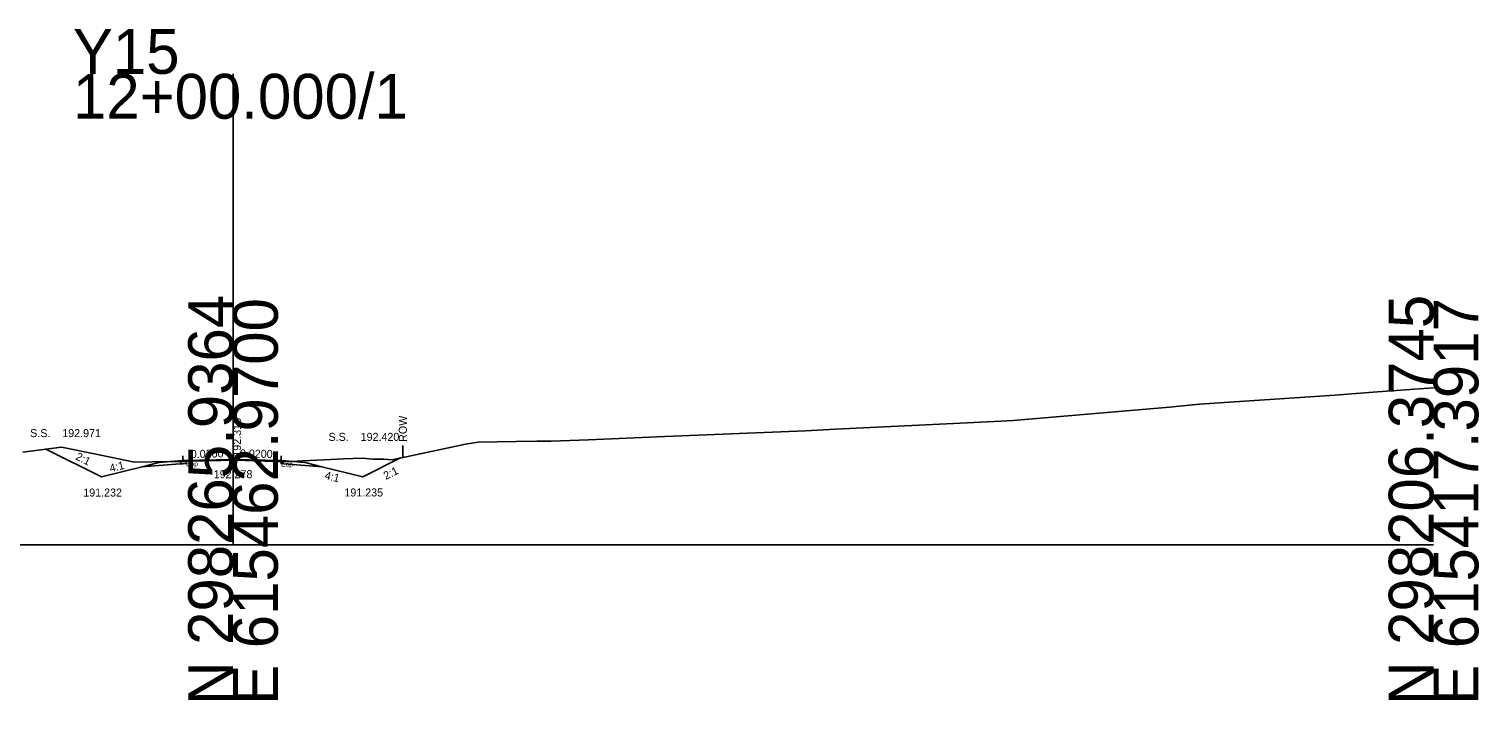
# Model space of a CAD drawing. Extents: x 517327 to 517505, y 114839 to 116885.
# Drawn here: x 517414.6 to 517505.2, y 116338.7 to 116380.6 of the extents above; entities that cross this region are included whole.
import ezdxf

# ---------------------------------------------------------------- set-up
doc = ezdxf.new("R2010")
doc.units = 0
for name, color, linetype in [('Exist XS Ground Line', 7, 'Continuous'), ('Old_Level_60', 7, 'Continuous'), ('Old_Level_63', 7, 'Continuous'), ('Prop XS Dump Level', 7, 'Continuous'), ('Prop XS Earthwork Shape', 7, 'Continuous'), ('Prop XS Elevation Labels', 7, 'Continuous'), ('Prop XS EOT Tick Mark', 7, 'Continuous'), ('Prop XS Exc Vertical Line 2', 7, 'Continuous'), ('Prop XS Finish Grade', 7, 'Continuous'), ('Prop XS Finish Grade Earthwork', 7, 'Continuous'), ('Prop XS Finish Grade Pavement', 7, 'Continuous'), ('Prop XS Hydro Elevations', 7, 'Continuous'), ('Prop XS Label Text', 7, 'Continuous'), ('Prop XS Pvmt Edge Slope', 7, 'Continuous'), ('Prop XS SE Text', 7, 'Continuous'), ('Prop XS Side Slope Text', 7, 'Continuous'), ('Prop XS Subgrade Earthwork', 7, 'Continuous'), ('Prop XS Suitable Common Exc Shape', 7, 'Continuous')]:
    doc.layers.add(name, color=color, linetype=linetype)

msp = doc.modelspace()

# ---------------------------------------------------------------- linework, layer by layer
at = {"layer": 'Exist XS Ground Line'}
for p, q in [((517496.208, 116357.708), (517498.866, 116357.912)), ((517498.866, 116357.912), (517502.365, 116358.167)), ((517476.097, 116356.129), (517485.868, 116356.954)), ((517485.868, 116356.954), (517487.752, 116357.134)), ((517487.752, 116357.134), (517496.208, 116357.708)), ((517465.004, 116355.581), (517472.38, 116355.938)), ((517472.38, 116355.938), (517475.332, 116356.09)), ((517475.332, 116356.09), (517476.097, 116356.129)), ((517449.569, 116354.918), (517454.336, 116355.115)), ((517454.336, 116355.115), (517463.12, 116355.475)), ((517463.12, 116355.475), (517465.004, 116355.581)), ((517414.235, 116354.149), (517416.658, 116354.466)), ((517416.658, 116354.466), (517418.601, 116354.054)), ((517437.316, 116353.676), (517441.897, 116354.636)), ((517441.897, 116354.636), (517442.676, 116354.764)), ((517442.676, 116354.764), (517445.036, 116354.813)), ((517445.036, 116354.813), (517446.339, 116354.823)), ((517446.339, 116354.823), (517447.246, 116354.824)), ((517447.246, 116354.824), (517449.569, 116354.918)), ((517418.601, 116354.054), (517421.204, 116353.527)), ((517421.204, 116353.527), (517423.427, 116353.56)), ((517423.427, 116353.56), (517424.439, 116353.566)), ((517424.439, 116353.566), (517424.822, 116353.576)), ((517424.822, 116353.576), (517427.494, 116353.646)), ((517427.494, 116353.646), (517429.958, 116353.557)), ((517429.958, 116353.557), (517430.376, 116353.545)), ((517430.376, 116353.545), (517431.07, 116353.572)), ((517431.07, 116353.572), (517431.699, 116353.599)), ((517431.699, 116353.599), (517433.06, 116353.671)), ((517433.06, 116353.671), (517434.29, 116353.722)), ((517434.29, 116353.722), (517435.426, 116353.775)), ((517435.426, 116353.775), (517436.094, 116353.704)), ((517436.094, 116353.704), (517436.795, 116353.701)), ((517436.795, 116353.701), (517437.316, 116353.676))]:
    msp.add_line(p, q, dxfattribs=at)
at = {"layer": 'Old_Level_63'}
for p, q in [((517427.365, 116348.365), (517427.365, 116377.77)), ((517352.365, 116348.365), (517427.365, 116348.365)), ((517427.365, 116348.365), (517502.365, 116348.365))]:
    msp.add_line(p, q, dxfattribs=at)
at = {"layer": 'Prop XS Dump Level'}
for p, q in [((517424.239, 116353.617), (517427.365, 116353.68)), ((517427.365, 116353.68), (517430.365, 116353.62))]:
    msp.add_line(p, q, dxfattribs=at)
at = {"layer": 'Prop XS Earthwork Shape'}
for points in [[(517415.661, 116354.336), (517416.658, 116354.466), (517418.601, 116354.054), (517421.204, 116353.527), (517423.427, 116353.56), (517424.44, 116353.567), (517424.438, 116353.431), (517424.239, 116353.427), (517424.045, 116353.423), (517422.739, 116353.319), (517421.69, 116353.235), (517419.139, 116352.597)], [(517435.426, 116353.775), (517436.094, 116353.704), (517436.795, 116353.701), (517437.316, 116353.676), (517437.836, 116353.785), (517435.465, 116352.6), (517432.914, 116353.237), (517431.865, 116353.321), (517430.559, 116353.426), (517430.365, 116353.43), (517430.363, 116353.546), (517431.07, 116353.572), (517431.699, 116353.599), (517433.06, 116353.671), (517434.29, 116353.722)]]:
    msp.add_lwpolyline(points, close=True, dxfattribs=at)
at = {"layer": 'Prop XS EOT Tick Mark'}
for p, q in [((517424.239, 116353.922), (517424.239, 116353.617)), ((517430.365, 116353.62), (517430.365, 116353.924))]:
    msp.add_line(p, q, dxfattribs=at)
at = {"layer": 'Prop XS Exc Vertical Line 2'}
msp.add_line((517437.974, 116354.564), (517437.974, 116353.814), dxfattribs=at)
at = {"layer": 'Prop XS Finish Grade'}
for p, q in [((517421.69, 116353.235), (517422.739, 116353.497)), ((517422.739, 116353.497), (517424.239, 116353.617)), ((517430.365, 116353.62), (517431.865, 116353.5)), ((517431.865, 116353.5), (517432.914, 116353.237))]:
    msp.add_line(p, q, dxfattribs=at)
at = {"layer": 'Prop XS Finish Grade Earthwork'}
for p, q in [((517415.661, 116354.336), (517419.139, 116352.597)), ((517419.139, 116352.597), (517421.69, 116353.235)), ((517432.914, 116353.237), (517435.465, 116352.6)), ((517435.465, 116352.6), (517437.836, 116353.785))]:
    msp.add_line(p, q, dxfattribs=at)
at = {"layer": 'Prop XS Finish Grade Pavement'}
for p, q in [((517427.365, 116353.68), (517424.239, 116353.617)), ((517430.365, 116353.62), (517427.365, 116353.68))]:
    msp.add_line(p, q, dxfattribs=at)
at = {"layer": 'Prop XS Pvmt Edge Slope'}
for p, q in [((517424.045, 116353.423), (517424.239, 116353.617)), ((517430.365, 116353.62), (517430.559, 116353.426))]:
    msp.add_line(p, q, dxfattribs=at)
at = {"layer": 'Prop XS Subgrade Earthwork'}
for p, q in [((517421.69, 116353.235), (517422.739, 116353.319)), ((517422.739, 116353.319), (517424.045, 116353.423)), ((517424.045, 116353.423), (517424.239, 116353.427)), ((517424.239, 116353.427), (517424.438, 116353.431)), ((517424.44, 116353.567), (517424.438, 116353.431)), ((517430.365, 116353.43), (517430.363, 116353.546)), ((517430.365, 116353.43), (517430.559, 116353.426)), ((517430.559, 116353.426), (517431.865, 116353.321)), ((517431.865, 116353.321), (517432.914, 116353.237))]:
    msp.add_line(p, q, dxfattribs=at)
at = {"layer": 'Prop XS Suitable Common Exc Shape'}
for points in [[(517423.427, 116353.56), (517424.439, 116353.566), (517424.438, 116353.431), (517424.239, 116353.427), (517424.045, 116353.423), (517422.739, 116353.319), (517421.69, 116353.235), (517419.139, 116352.597), (517415.661, 116354.336), (517416.658, 116354.466), (517418.601, 116354.054), (517421.204, 116353.527)], [(517437.316, 116353.676), (517437.836, 116353.785), (517435.465, 116352.6), (517432.914, 116353.237), (517431.865, 116353.321), (517430.559, 116353.426), (517430.365, 116353.43), (517430.376, 116353.545), (517431.07, 116353.572), (517431.699, 116353.599), (517433.06, 116353.671), (517434.29, 116353.722), (517435.426, 116353.775), (517436.094, 116353.704), (517436.795, 116353.701)]]:
    msp.add_lwpolyline(points, close=True, dxfattribs=at)

# ---------------------------------------------------------------- texts
at = {"layer": 'Old_Level_60'}
msp.add_text('192.278', height=0.5, dxfattribs=at).set_placement((517426.158, 116352.522))
at = {"layer": 'Old_Level_63'}
for s, p in [('Y15', (517417.362, 116377.77)), ('12+00.000/1', (517417.365, 116374.97))]:
    msp.add_text(s, height=2.8, dxfattribs=at).set_placement(p)
for s, p in [('N 298265.9364', (517427.365, 116338.365)), ('E 615462.9700', (517430.165, 116338.365)), ('N 298206.3745', (517502.365, 116338.364)), ('E 615417.3917', (517505.165, 116338.364))]:
    msp.add_text(s, height=2.8, rotation=90, dxfattribs=at).set_placement(p)
at = {"layer": 'Prop XS Dump Level'}
for s, height, p in [('Case1', 0.0122, (517422.739, 116353.485)), ('Eop', 0.3, (517424.438, 116353.266)), ('Eop', 0.3, (517430.375, 116353.245)), ('Case1', 0.0122, (517431.865, 116353.487))]:
    msp.add_text(s, height=height, dxfattribs=at).set_placement(p)
at = {"layer": 'Prop XS Elevation Labels'}
msp.add_text(' 192.315', height=0.5, rotation=90, dxfattribs=at).set_placement((517427.865, 116353.68))
at = {"layer": 'Prop XS Exc Vertical Line 2'}
msp.add_text('ROW', height=0.5, rotation=90, dxfattribs=at).set_placement((517438.224, 116354.789))
at = {"layer": 'Prop XS Hydro Elevations'}
for s, p in [('S.S.    192.971', (517414.692, 116355.086)), ('S.S.    192.420', (517433.332, 116354.852))]:
    msp.add_text(s, height=0.5, dxfattribs=at).set_placement(p)
at = {"layer": 'Prop XS Label Text'}
for rotation, p in [(14.03624, (517419.713, 116352.887)), (345.96376, (517433.052, 116352.484))]:
    msp.add_text('4:1', height=0.5, rotation=rotation, dxfattribs=at).set_placement(p)
at = {"layer": 'Prop XS SE Text'}
for rotation, p in [(1.14577, (517424.73, 116353.779)), (358.85425, (517427.792, 116353.823))]:
    msp.add_text('0.0200', height=0.5, rotation=rotation, dxfattribs=at).set_placement(p)
at = {"layer": 'Prop XS Side Slope Text'}
for rotation, p in [(333.43495, (517417.481, 116353.712)), (26.56505, (517436.917, 116352.408))]:
    msp.add_text('2:1', height=0.5, rotation=rotation, dxfattribs=at).set_placement(p)
for s, p in [('191.232', (517418.008, 116351.377)), ('191.235', (517434.322, 116351.38))]:
    msp.add_text(s, height=0.5, dxfattribs=at).set_placement(p)

doc.saveas('drawing.dxf')
